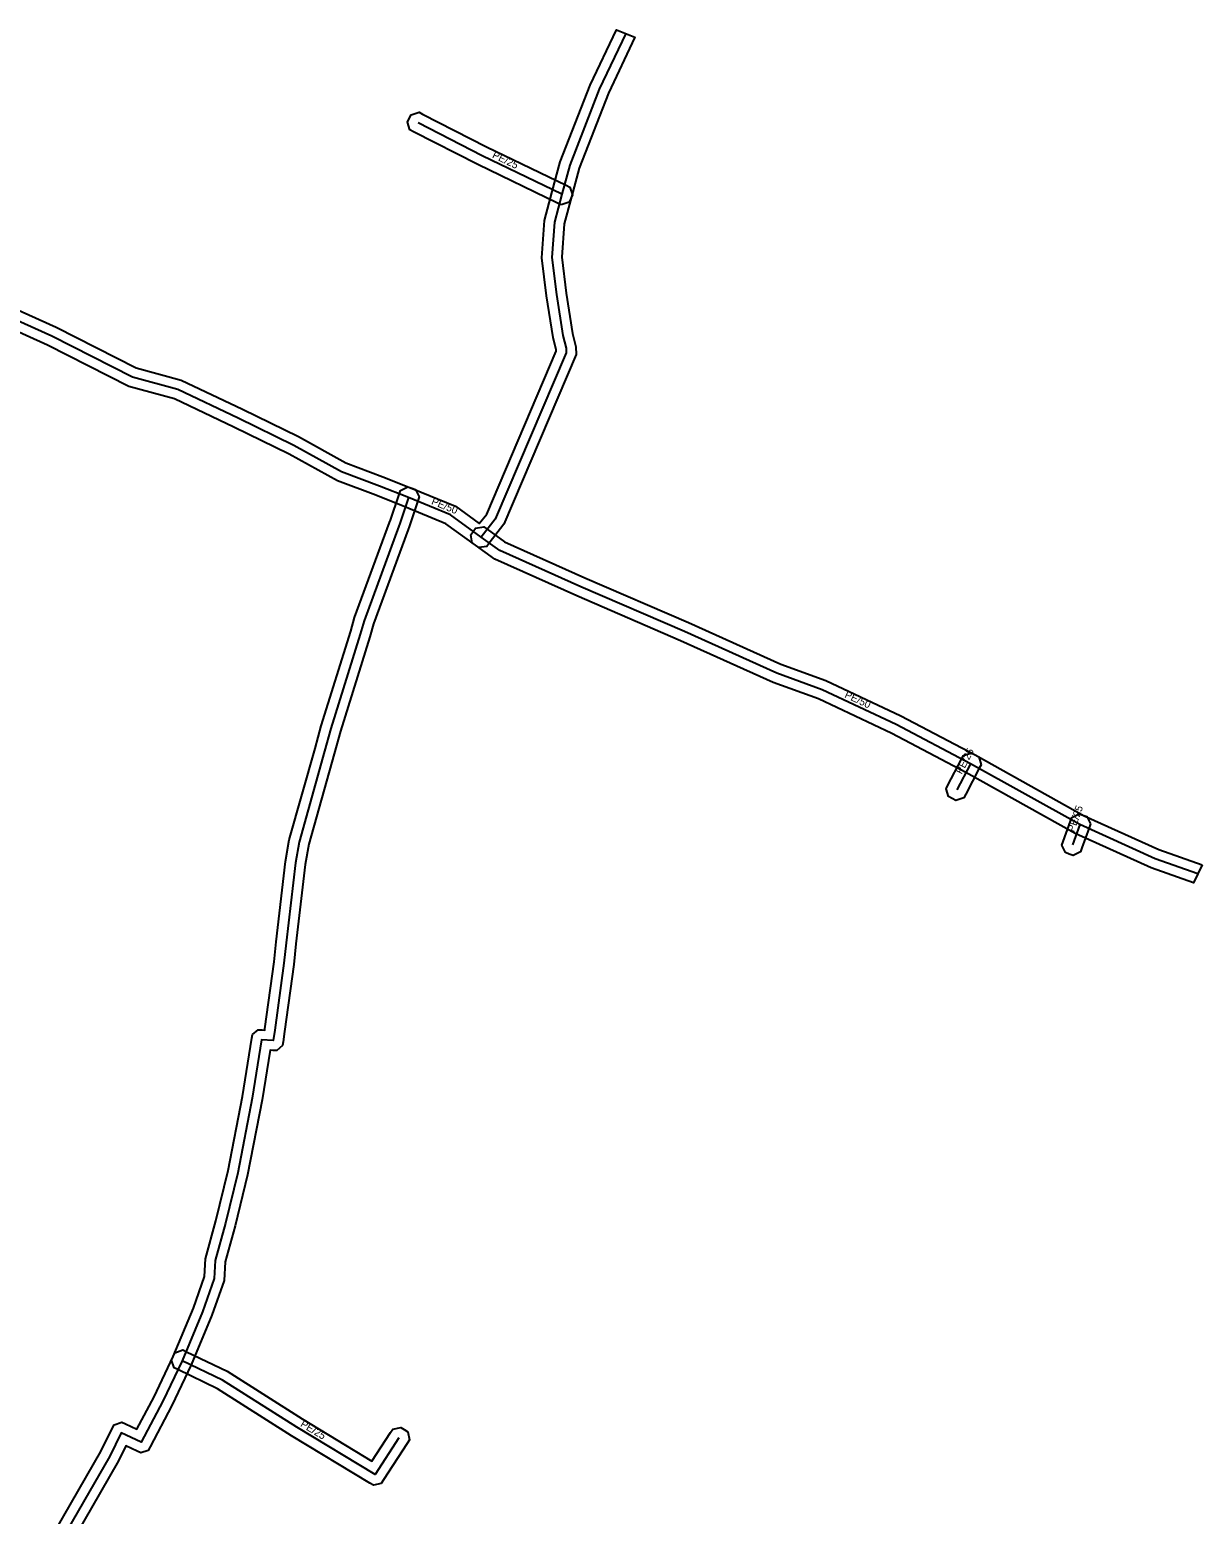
# Model space of a CAD drawing. Extents: x -681131 to -680872, y -1058347 to -1057759.
# Drawn here: x -680989.6 to -680871.5, y -1057908.3 to -1057758.9 of the extents above; entities that cross this region are included whole.
import ezdxf

# ---------------------------------------------------------------- set-up
doc = ezdxf.new("R2010")
doc.units = 0
for name, color, linetype in [('1', 7, 'Continuous'), ('24', 7, 'Continuous'), ('30', 7, 'Continuous')]:
    doc.layers.add(name, color=color, linetype=linetype)

msp = doc.modelspace()

# ---------------------------------------------------------------- linework, layer by layer
at = {"layer": '1'}
for points in [[(-680996.26, -1057784.67), (-680986.94, -1057788.87), (-680978.89, -1057792.96), (-680974.33, -1057794.19), (-680968.17, -1057797.13), (-680962.54, -1057799.88), (-680957.78, -1057802.51), (-680954.03, -1057803.93), (-680951.08, -1057805.09), (-680946.73, -1057806.89), (-680944.33, -1057808.62), (-680943.59, -1057807.67), (-680936.59, -1057791.27), (-680936.59, -1057791.14), (-680936.91, -1057789.9), (-680937.56, -1057785.71), (-680938.05, -1057781.89), (-680937.76, -1057778.12), (-680936.99, -1057775.23), (-680936.18, -1057772.24), (-680933.17, -1057764.51), (-680930.51, -1057758.93), (-680928.66, -1057759.68), (-680931.33, -1057765.31), (-680934.28, -1057772.86), (-680935.05, -1057775.75), (-680935.78, -1057778.46), (-680936.04, -1057781.83), (-680935.58, -1057785.43), (-680934.95, -1057789.5), (-680934.6, -1057790.84), (-680934.57, -1057791.63), (-680941.85, -1057808.69), (-680943.34, -1057810.61), (-680943.59, -1057810.93), (-680944.39, -1057811.05), (-680944.71, -1057810.81), (-680947.71, -1057808.65), (-680951.83, -1057806.95), (-680954.75, -1057805.79), (-680958.62, -1057804.33), (-680963.46, -1057801.66), (-680969.04, -1057798.93), (-680975.03, -1057796.07), (-680979.61, -1057794.84), (-680987.8, -1057790.67), (-680997.1, -1057786.48)], [(-680987.7, -1057911.18), (-680982.42, -1057902.02), (-680981.28, -1057899.69), (-680981.1, -1057899.32), (-680980.32, -1057899.05), (-680979.95, -1057899.23), (-680978.8, -1057899.77), (-680977.07, -1057896.5), (-680975.16, -1057892.47), (-680973.12, -1057887.59), (-680972.01, -1057884.4), (-680971.91, -1057882.62), (-680970.85, -1057878.79), (-680969.63, -1057873.75), (-680968.18, -1057866.28), (-680967.24, -1057860.43), (-680967.18, -1057860.05), (-680966.58, -1057859.57), (-680966.2, -1057859.59), (-680965.94, -1057859.6), (-680965.92, -1057859.48), (-680965, -1057852.75), (-680964.78, -1057850.71), (-680963.83, -1057842.65), (-680963.46, -1057840.46), (-680960.86, -1057831.26), (-680960.24, -1057828.98), (-680957.27, -1057819.47), (-680956.89, -1057818.1), (-680953.36, -1057808.54), (-680953.27, -1057808.3), (-680952.41, -1057805.7), (-680952.28, -1057805.31), (-680951.54, -1057804.94), (-680951.14, -1057805.07), (-680950.75, -1057805.2), (-680950.38, -1057805.94), (-680950.51, -1057806.34), (-680951.39, -1057808.96), (-680951.49, -1057809.23), (-680954.99, -1057818.72), (-680955.35, -1057820.03), (-680958.32, -1057829.54), (-680958.94, -1057831.8), (-680961.5, -1057840.9), (-680961.85, -1057842.93), (-680962.8, -1057850.93), (-680963.02, -1057852.99), (-680963.94, -1057859.74), (-680964.08, -1057860.78), (-680964.13, -1057861.17), (-680964.73, -1057861.67), (-680965.12, -1057861.65), (-680965.4, -1057861.63), (-680966.2, -1057866.64), (-680967.67, -1057874.17), (-680968.91, -1057879.29), (-680969.93, -1057882.94), (-680970.03, -1057884.8), (-680971.26, -1057888.31), (-680973.34, -1057893.29), (-680975.29, -1057897.4), (-680977.48, -1057901.55), (-680977.66, -1057901.9), (-680978.42, -1057902.16), (-680978.79, -1057901.99), (-680979.92, -1057901.45), (-680980.66, -1057902.96), (-680985.96, -1057912.18)]]:
    msp.add_lwpolyline(points, dxfattribs=at)
for points in [[(-680936.08, -1057776.57), (-680936.45, -1057776.39), (-680944.49, -1057772.51), (-680950.95, -1057769.21), (-680951.31, -1057769.02), (-680951.57, -1057768.23), (-680951.38, -1057767.86), (-680951.19, -1057767.5), (-680950.4, -1057767.24), (-680950.04, -1057767.43), (-680943.6, -1057770.71), (-680935.58, -1057774.59), (-680935.21, -1057774.77), (-680934.94, -1057775.55), (-680935.12, -1057775.93), (-680935.3, -1057776.3)], [(-680871.55, -1057842.99), (-680872.45, -1057844.79), (-680876.69, -1057843.29), (-680884.34, -1057839.81), (-680895.37, -1057833.68), (-680902.81, -1057829.77), (-680910.2, -1057826.28), (-680914.75, -1057824.63), (-680924.07, -1057820.42), (-680934.5, -1057815.92), (-680942.78, -1057812.2), (-680944.71, -1057810.81), (-680945.05, -1057810.57), (-680945.18, -1057809.75), (-680944.94, -1057809.42), (-680944.7, -1057809.08), (-680943.88, -1057808.95), (-680943.55, -1057809.19), (-680941.78, -1057810.46), (-680933.7, -1057814.08), (-680923.27, -1057818.58), (-680913.99, -1057822.77), (-680909.44, -1057824.44), (-680901.91, -1057827.98), (-680894.41, -1057831.92), (-680883.44, -1057838.03), (-680875.94, -1057841.43)], [(-680893.81, -1057832.9), (-680894, -1057833.26), (-680895.37, -1057835.88), (-680895.57, -1057836.25), (-680896.36, -1057836.5), (-680896.72, -1057836.31), (-680897.09, -1057836.11), (-680897.34, -1057835.32), (-680897.15, -1057834.96), (-680895.78, -1057832.34), (-680895.58, -1057831.97), (-680894.79, -1057831.72), (-680894.43, -1057831.91), (-680894.06, -1057832.11)], [(-680882.81, -1057838.86), (-680882.95, -1057839.25), (-680883.67, -1057841.28), (-680883.81, -1057841.68), (-680884.55, -1057842.03), (-680884.94, -1057841.89), (-680885.33, -1057841.75), (-680885.69, -1057841.01), (-680885.55, -1057840.62), (-680884.83, -1057838.59), (-680884.69, -1057838.2), (-680883.95, -1057837.84), (-680883.56, -1057837.98), (-680883.17, -1057838.12)], [(-680951.37, -1057900.85), (-680951.59, -1057901.2), (-680953.99, -1057904.88), (-680954.21, -1057905.22), (-680955, -1057905.4), (-680955.35, -1057905.19), (-680963.24, -1057900.43), (-680970.69, -1057895.7), (-680974.68, -1057893.78), (-680975.06, -1057893.6), (-680975.33, -1057892.82), (-680975.15, -1057892.45), (-680974.97, -1057892.07), (-680974.19, -1057891.8), (-680973.82, -1057891.98), (-680969.71, -1057893.94), (-680962.18, -1057898.73), (-680955.14, -1057902.98), (-680953.27, -1057900.1), (-680953.04, -1057899.76), (-680952.23, -1057899.59), (-680951.88, -1057899.81), (-680951.54, -1057900.04)]]:
    msp.add_lwpolyline(points, close=True, dxfattribs=at)
at = {"layer": '24'}
for points in [[(-680929.58, -1057759.3), (-680932.25, -1057764.91), (-680935.23, -1057772.55), (-680936.02, -1057775.49), (-680936.77, -1057778.29), (-680937.04, -1057781.86), (-680936.57, -1057785.57), (-680935.93, -1057789.7), (-680935.6, -1057790.99), (-680935.58, -1057791.45), (-680942.72, -1057808.18), (-680944.13, -1057810), (-680947.22, -1057807.77), (-680951.46, -1057806.02), (-680954.39, -1057804.86), (-680958.2, -1057803.42), (-680963, -1057800.77), (-680968.6, -1057798.03), (-680974.68, -1057795.13), (-680979.25, -1057793.9), (-680987.37, -1057789.77), (-680996.68, -1057785.57), (-681004.12, -1057781.93)], [(-680936.02, -1057775.49), (-680944.05, -1057771.61), (-680950.49, -1057768.32)], [(-680951.46, -1057806.02), (-680952.33, -1057808.63), (-680952.43, -1057808.89), (-680955.94, -1057818.41), (-680956.31, -1057819.75), (-680959.28, -1057829.26), (-680959.9, -1057831.53), (-680962.48, -1057840.68), (-680962.84, -1057842.79), (-680963.79, -1057850.82), (-680964.01, -1057852.87), (-680964.93, -1057859.61), (-680965.07, -1057860.65), (-680966.25, -1057860.59), (-680967.19, -1057866.46), (-680968.65, -1057873.96), (-680969.88, -1057879.04), (-680970.92, -1057882.78), (-680971.02, -1057884.6), (-680972.19, -1057887.95), (-680974.25, -1057892.88), (-680976.18, -1057896.95), (-680978.36, -1057901.08), (-680980.38, -1057900.13), (-680981.54, -1057902.49), (-680986.83, -1057911.68)], [(-680872, -1057843.89), (-680876.31, -1057842.36), (-680883.89, -1057838.92), (-680894.89, -1057832.8), (-680902.36, -1057828.87), (-680909.82, -1057825.36), (-680914.37, -1057823.7), (-680923.67, -1057819.5), (-680934.1, -1057815), (-680942.28, -1057811.33), (-680944.13, -1057810)], [(-680894.89, -1057832.8), (-680896.26, -1057835.42)], [(-680883.89, -1057838.92), (-680884.61, -1057840.95)], [(-680952.43, -1057900.65), (-680954.83, -1057904.33), (-680962.71, -1057899.58), (-680970.2, -1057894.82), (-680974.25, -1057892.88)]]:
    msp.add_lwpolyline(points, dxfattribs=at)

# ---------------------------------------------------------------- texts
at = {"layer": '30'}
for s, rotation, p in [('PE/25', 334.2107, (-680943.09, -1057771.78)), ('PE/50', 337.5723, (-680949.22, -1057806.66)), ('PE/50', 334.8026, (-680907.62, -1057826.1)), ('PE/25', 62.3949, (-680895.78, -1057833.91)), ('PE/25', 70.4714, (-680884.45, -1057839.74)), ('PE/25', 328.9188, (-680962.41, -1057899.44))]:
    msp.add_text(s, height=0.75, rotation=rotation, dxfattribs=at).set_placement(p)

doc.saveas('drawing.dxf')
